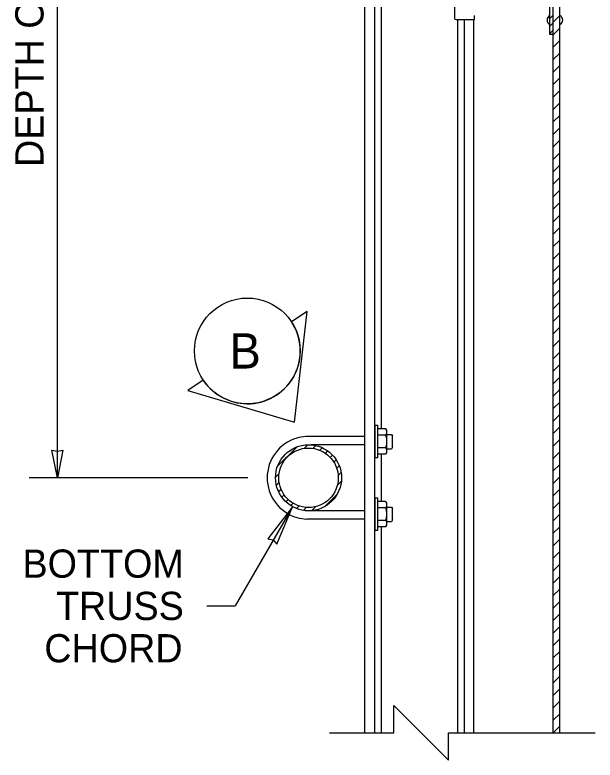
# Model space of a CAD drawing. Extents: x 99862 to 103151, y 100000 to 102076.
# Drawn here: x 101323.4 to 101652.6, y 100737.7 to 101160.4 of the extents above; entities that cross this region are included whole.
import ezdxf

# ---------------------------------------------------------------- set-up
doc = ezdxf.new("R2010")
doc.units = 0
for name, color, linetype in [('Level 1', 7, 'Continuous'), ('Level 10', 7, 'Continuous'), ('Level 13', 7, 'Continuous'), ('Level 14', 7, 'Continuous'), ('Level 15', 7, 'Continuous'), ('Level 2', 7, 'Continuous'), ('Level 20', 7, 'Continuous'), ('Level 27', 7, 'Continuous'), ('Level 4', 7, 'Continuous'), ('Level 5', 7, 'Continuous'), ('Level 8', 7, 'Continuous')]:
    doc.layers.add(name, color=color, linetype=linetype)

msp = doc.modelspace()

# ---------------------------------------------------------------- linework, layer by layer
at = {"layer": 'Level 1'}
for p, q in [((101628.87, 101156.28), (101632.62, 101160.03)), ((101628.87, 101149.21), (101632.62, 101152.96)), ((101628.87, 101142.14), (101632.62, 101145.89)), ((101628.87, 101135.07), (101632.62, 101138.82)), ((101628.87, 101128), (101632.62, 101131.75)), ((101628.87, 101120.93), (101632.62, 101124.68)), ((101628.87, 101113.85), (101632.62, 101117.6)), ((101628.87, 101106.78), (101632.62, 101110.53)), ((101628.87, 101099.71), (101632.62, 101103.46)), ((101628.87, 101092.64), (101632.62, 101096.39)), ((101628.87, 101085.57), (101632.62, 101089.32)), ((101628.87, 101078.5), (101632.62, 101082.25)), ((101628.87, 101071.43), (101632.62, 101075.18)), ((101628.87, 101064.36), (101632.62, 101068.11)), ((101628.87, 101057.29), (101632.62, 101061.04)), ((101628.87, 101050.21), (101632.62, 101053.96)), ((101628.87, 101043.14), (101632.62, 101046.89)), ((101628.87, 101036.07), (101632.62, 101039.82)), ((101628.87, 101029), (101632.62, 101032.75)), ((101628.87, 101021.93), (101632.62, 101025.68)), ((101628.87, 101014.86), (101632.62, 101018.61)), ((101628.87, 101007.79), (101632.62, 101011.54)), ((101628.87, 101000.72), (101632.62, 101004.47)), ((101628.87, 100993.65), (101632.62, 100997.4)), ((101628.87, 100986.57), (101632.62, 100990.32)), ((101628.87, 100979.5), (101632.62, 100983.25)), ((101628.87, 100972.43), (101632.62, 100976.18)), ((101628.87, 100965.36), (101632.62, 100969.11)), ((101628.87, 100958.29), (101632.62, 100962.04)), ((101628.87, 100951.22), (101632.62, 100954.97)), ((101628.87, 100944.15), (101632.62, 100947.9)), ((101628.87, 100937.08), (101632.62, 100940.83)), ((101628.87, 100930.01), (101632.62, 100933.76)), ((101628.87, 100922.94), (101632.62, 100926.69)), ((101628.87, 100915.86), (101632.62, 100919.61)), ((101628.87, 100908.79), (101632.62, 100912.54)), ((101628.87, 100901.72), (101632.62, 100905.47)), ((101628.87, 100894.65), (101632.62, 100898.4)), ((101628.87, 100887.58), (101632.62, 100891.33)), ((101628.87, 100880.51), (101632.62, 100884.26)), ((101628.87, 100873.44), (101632.62, 100877.19)), ((101628.87, 100866.37), (101632.62, 100870.12)), ((101628.87, 100859.3), (101632.62, 100863.05)), ((101628.87, 100852.22), (101632.62, 100855.97)), ((101628.87, 100845.15), (101632.62, 100848.9)), ((101628.87, 100838.08), (101632.62, 100841.83)), ((101628.87, 100831.01), (101632.62, 100834.76)), ((101628.87, 100823.94), (101632.62, 100827.69)), ((101628.87, 100816.87), (101632.62, 100820.62)), ((101628.87, 100809.8), (101632.62, 100813.55)), ((101628.87, 100802.73), (101632.62, 100806.48)), ((101628.87, 100795.66), (101632.62, 100799.41)), ((101628.87, 100788.59), (101632.62, 100792.34)), ((101628.87, 100781.51), (101632.62, 100785.26)), ((101628.87, 100774.44), (101632.62, 100778.19)), ((101628.87, 100767.37), (101632.62, 100771.12)), ((101628.87, 100760.3), (101632.62, 100764.05)), ((101628.87, 100753.23), (101632.62, 100756.98))]:
    msp.add_line(p, q, dxfattribs=at)
for points in [[(101628.87, 100753.22), (101628.87, 101110.01), (101628.87, 101590.01)], [(101632.62, 100753.22), (101632.62, 101107.92), (101632.62, 101590.01)]]:
    msp.add_open_spline(points, degree=2, dxfattribs=at)
at = {"layer": 'Level 10'}
for p, q in [((101529.22, 100925.64), (101529.22, 100922.06)), ((101533.78, 100925.64), (101529.22, 100925.64)), ((101533.78, 100925.64), (101534.34, 100924.68)), ((101534.34, 100924.68), (101534.34, 100923.93)), ((101533.78, 100922.06), (101529.22, 100922.06)), ((101534.34, 100923.93), (101534.34, 100923.76)), ((101534.34, 100923.76), (101534.34, 100918.63)), ((101534.34, 100922.46), (101534.34, 100914.19)), ((101534.34, 100918.63), (101534.34, 100918.32)), ((101534.34, 100918.32), (101534.34, 100913.14)), ((101533.78, 100914.89), (101529.22, 100914.89)), ((101534.34, 100912.27), (101533.78, 100911.31)), ((101534.34, 100913.14), (101534.34, 100913.06)), ((101534.34, 100913.06), (101534.34, 100912.27)), ((101533.78, 100911.31), (101529.22, 100911.31)), ((101529.18, 100884.39), (101529.18, 100880.81)), ((101533.75, 100884.39), (101529.18, 100884.39)), ((101533.75, 100884.39), (101534.3, 100883.43)), ((101534.3, 100883.43), (101534.3, 100882.68)), ((101534.3, 100882.68), (101534.3, 100882.51)), ((101534.3, 100882.51), (101534.3, 100877.38)), ((101533.75, 100880.81), (101529.18, 100880.81)), ((101534.3, 100881.21), (101534.3, 100872.94)), ((101533.75, 100873.64), (101529.18, 100873.64)), ((101534.3, 100877.38), (101534.3, 100877.07)), ((101534.3, 100877.07), (101534.3, 100871.89)), ((101533.75, 100870.06), (101529.18, 100870.06)), ((101534.3, 100871.02), (101533.75, 100870.06)), ((101534.3, 100871.89), (101534.3, 100871.81)), ((101534.3, 100871.81), (101534.3, 100871.02))]:
    msp.add_line(p, q, dxfattribs=at)
for points in [[(101529.22, 100927.67), (101529.22, 100909.28), (101527.84, 100909.28), (101527.84, 100927.67)], [(101529.18, 100886.42), (101529.18, 100868.03), (101527.8, 100868.03), (101527.8, 100886.42)]]:
    msp.add_lwpolyline(points, close=True, dxfattribs=at)
for points, degree in [([(101533.79, 100925.63), (101533.79, 100925.63), (101533.79, 100925.64), (101533.78, 100925.64)], 2), ([(101534.34, 100923.76), (101534.32, 100923.18), (101534.11, 100922.62), (101533.78, 100922.06)], 2), ([(101533.78, 100922.06), (101533.95, 100921.5), (101534.08, 100920.93), (101534.27, 100919.78), (101534.33, 100919.21), (101534.34, 100918.63)], 3), ([(101534.34, 100918.32), (101534.33, 100917.74), (101534.27, 100917.15), (101534.08, 100916.01), (101533.94, 100915.45), (101533.78, 100914.89)], 3), ([(101533.78, 100914.89), (101534.11, 100914.32), (101534.33, 100913.74), (101534.34, 100913.14)], 2), ([(101534.34, 100913.06), (101534.33, 100912.76), (101534.28, 100912.47), (101534.08, 100911.88), (101533.95, 100911.6), (101533.78, 100911.31)], 3), ([(101533.76, 100884.38), (101533.75, 100884.38), (101533.75, 100884.39), (101533.75, 100884.39)], 2), ([(101534.3, 100882.51), (101534.28, 100881.93), (101534.07, 100881.37), (101533.75, 100880.81)], 2), ([(101533.75, 100880.81), (101533.91, 100880.25), (101534.05, 100879.68), (101534.24, 100878.53), (101534.29, 100877.96), (101534.3, 100877.38)], 3), ([(101534.3, 100877.07), (101534.29, 100876.49), (101534.24, 100875.9), (101534.04, 100874.76), (101533.91, 100874.2), (101533.75, 100873.64)], 3), ([(101533.75, 100873.64), (101534.08, 100873.07), (101534.29, 100872.49), (101534.3, 100871.89)], 2), ([(101534.3, 100871.81), (101534.3, 100871.51), (101534.24, 100871.22), (101534.05, 100870.63), (101533.91, 100870.35), (101533.75, 100870.06)], 3)]:
    msp.add_open_spline(points, degree=degree, dxfattribs=at)
at = {"layer": 'Level 13'}
for centre, start, end in [((101628.15, 101157.52), 114.2376, 245.7624), ((101631.46, 101157.52), 0, 65.7624), ((101631.46, 101157.52), 294.2376, 0)]:
    msp.add_arc(centre, 2.81, start, end, dxfattribs=at)
at = {"layer": 'Level 14'}
for p, q in [((101487.61, 100914.57), (101489.65, 100916.61)), ((101492.54, 100914.55), (101494.14, 100916.15)), ((101472.46, 100904.37), (101483.52, 100915.42)), ((101496.42, 100913.48), (101497.82, 100914.88)), ((101499.63, 100911.74), (101500.96, 100913.07)), ((101502.29, 100909.45), (101503.6, 100910.76)), ((101504.43, 100906.64), (101505.77, 100907.98)), ((101506.01, 100903.27), (101507.46, 100904.72)), ((101471.29, 100898.25), (101473.32, 100900.28)), ((101506.85, 100899.16), (101508.51, 100900.82)), ((101471.75, 100893.76), (101473.34, 100895.35)), ((101506.39, 100893.75), (101508.67, 100896.03)), ((101473.01, 100890.07), (101474.41, 100891.47)), ((101474.81, 100886.92), (101476.15, 100888.26)), ((101499.01, 100881.42), (101506.4, 100888.81)), ((101477.13, 100884.29), (101478.44, 100885.6)), ((101479.9, 100882.11), (101481.24, 100883.45)), ((101483.18, 100880.44), (101484.62, 100881.88)), ((101487.08, 100879.39), (101488.73, 100881.04)), ((101491.88, 100879.24), (101494.14, 100881.5))]:
    msp.add_line(p, q, dxfattribs=at)
for radius in [18.75, 16.88]:
    msp.add_circle((101490.02, 100897.87), radius, dxfattribs=at)
at = {"layer": 'Level 15'}
for p, q in [((101347.52, 100897.9), (101347.76, 101441.16)), ((101455.52, 100897.87), (101331.52, 100897.87)), ((101480.88, 100881.48), (101448.38, 100825.18)), ((101432.38, 100825.18), (101448.38, 100825.18))]:
    msp.add_line(p, q, dxfattribs=at)
for points in [[(101347.52, 100897.9), (101344.45, 100913.62), (101347.53, 100912.89), (101350.61, 100913.62)], [(101480.88, 100881.48), (101466.88, 100863.2), (101469.99, 100862.62), (101472.05, 100860.21)]]:
    msp.add_lwpolyline(points, close=True, dxfattribs=at)
msp.add_lwpolyline([(101501.99, 100753.22), (101538.47, 100753.22), (101538.47, 100768.7), (101569.44, 100737.73), (101569.44, 100753.22), (101652.62, 100753.22)], dxfattribs=at)
at = {"layer": 'Level 2'}
for p, q in [((101521.99, 100753.22), (101521.99, 101590.01)), ((101527.62, 100753.22), (101527.62, 101590.01)), ((101578.24, 101157.8), (101578.24, 100753.22)), ((101583.87, 100753.22), (101583.87, 101157.8))]:
    msp.add_line(p, q, dxfattribs=at)
at = {"layer": 'Level 20'}
for p, q in [((101489.17, 100992.24), (101480.33, 100986.39)), ((101482.04, 100929.42), (101489.17, 100992.24)), ((101430.29, 100953.3), (101421.45, 100947.45)), ((101421.45, 100947.45), (101482.04, 100929.42))]:
    msp.add_line(p, q, dxfattribs=at)
msp.add_circle((101455.31, 100969.84), 30, dxfattribs=at)
msp.add_arc((101455.31, 100969.84), 30, 213.4778, 33.4822, dxfattribs=at)
at = {"layer": 'Level 27'}
for p, q in [((101531.37, 100925.64), (101531.37, 101410.1)), ((101574.49, 101157.8), (101574.49, 100753.22)), ((101531.16, 100911.31), (101531.16, 100884.39)), ((101531.37, 100753.22), (101531.37, 100870.06))]:
    msp.add_line(p, q, dxfattribs=at)
at = {"layer": 'Level 4'}
for p, q in [((101626.99, 101149.37), (101626.99, 101165.68)), ((101626.99, 101158.38), (101628.87, 101160.25)), ((101626.99, 101154.13), (101628.87, 101156.01)), ((101626.99, 101149.89), (101628.87, 101151.77)), ((101628.87, 101149.37), (101626.99, 101149.37))]:
    msp.add_line(p, q, dxfattribs=at)
at = {"layer": 'Level 5'}
for p, q in [((101572.82, 101177.88), (101572.82, 101158.35)), ((101573.83, 101157.8), (101577.35, 101157.8)), ((101577.35, 101157.8), (101581.8, 101157.8)), ((101581.8, 101157.8), (101584.13, 101157.8)), ((101584.13, 101157.8), (101584.13, 101160.16))]:
    msp.add_line(p, q, dxfattribs=at)
msp.add_ellipse((101579.19, 101158.35), major_axis=(6.38, 0), ratio=0.158525, start_param=3.141585, end_param=3.712124, dxfattribs=at)
at = {"layer": 'Level 8'}
for p, q in [((101521.99, 100921.31), (101488.48, 100921.31)), ((101534.34, 100922.46), (101537.18, 100922.46)), ((101537.18, 100922.46), (101537.75, 100921.48)), ((101537.75, 100915.19), (101537.75, 100921.48)), ((101521.99, 100916.56), (101491.43, 100916.56)), ((101537.18, 100914.19), (101534.34, 100914.19)), ((101537.75, 100915.19), (101537.17, 100914.19)), ((101521.99, 100879.14), (101490.9, 100879.14)), ((101521.99, 100879.13), (101520.96, 100879.13)), ((101534.3, 100881.21), (101537.15, 100881.21)), ((101537.15, 100881.21), (101537.71, 100880.23)), ((101537.71, 100873.94), (101537.71, 100880.23)), ((101521.99, 100874.39), (101489.06, 100874.39)), ((101537.71, 100873.94), (101537.14, 100872.94)), ((101537.15, 100872.94), (101534.3, 100872.94))]:
    msp.add_line(p, q, dxfattribs=at)
for start, end in [(106.5978, 253.4022), (93.921, 106.5978), (253.4022, 267.5513)]:
    msp.add_arc((101490.02, 100897.87), 23.5, start, end, dxfattribs=at)

# ---------------------------------------------------------------- texts
at = {"layer": 'Level 20'}
msp.add_text('DEPTH OF TRUSS', height=16, rotation=90, dxfattribs=at).set_placement((101339.64, 101074.16))
for s, height, p in [('B', 20, (101445.12, 100959.84)), ('BOTTOM', 16, (101327.71, 100841.19)), ('TRUSS', 16, (101346.73, 100817.19)), ('CHORD', 16, (101340.09, 100793.19))]:
    msp.add_text(s, height=height, dxfattribs=at).set_placement(p)

doc.saveas('drawing.dxf')
